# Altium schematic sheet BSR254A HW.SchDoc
size 431 x 279 mm; Date: Not shown in title block; ApprovedBy: Not shown in title block; CheckedBy: Not shown in title block; Author: Not shown in title block; CompanyName: Not shown in title block; DrawnBy: Tony Jacobs; Engineer: Not shown in title block; Organization: Not shown in title block; Address1: Not shown in title block; Address2: Not shown in title block; Address3: Not shown in title block; Address4: Not shown in title block; DocumentNumber: 2; Revision: Use project parameter SCH_Rev; SheetNumber: 2; SheetTotal: 2; PageSetup: Record=PageOptions¦CenterHorizontal=True¦CenterVertical=True¦PrintScale=1.00¦XCorrection=1.00¦YCorrection=1.00¦PrintKind=0¦BorderSize=5000000¦LeftOffset=0¦BottomOffset=0¦Orientation=2¦PaperLength=1000¦PaperWidth=1000¦Scale=100¦PaperSource=15¦PrintQuality=600¦MediaType=1¦DitherType=10¦PaperKind=Letter¦PrintScaleMode=1
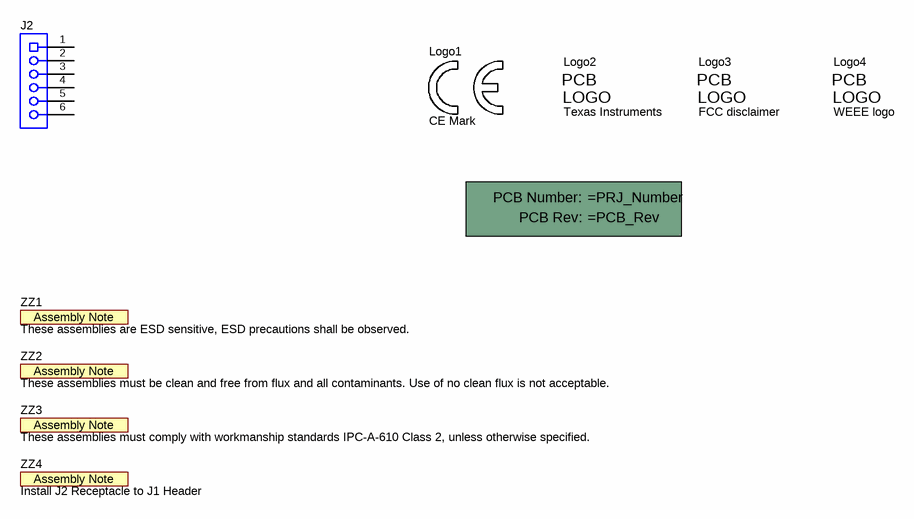
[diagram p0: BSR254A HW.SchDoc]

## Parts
!PCB1  Printed Circuit Board  (value not drawn)  (mechanical)
J2  SSW-106-01-G-S  [Samtec_SSW-106-01-x-S]  (value not drawn)  (mechanical)
Logo1  CE Mark  [CE_Mark_5mm]  (no BOM)
Logo2  Texas Instruments  [TI_Symbol_Overlay_Small]  (no BOM)
Logo3  FCC disclaimer  [FCC_disclaimer]  (no BOM)
Logo4  WEEE logo  [WEEE_Minimum]  (no BOM)
ZZ1  These assemblies are ESD sensitive, ESD precautions shall be observed.  [AssemblyNote]  (no BOM)
ZZ2  These assemblies must be clean and free from flux and all contaminants. Use of no clean flux is not acceptable.  [AssemblyNote]  (no BOM)
ZZ3  These assemblies must comply with workmanship standards IPC-A-610 Class 2, unless otherwise specified.  [AssemblyNote]  (no BOM)
ZZ4  Install J2 Receptacle to J1 Header  [AssemblyNote]  (no BOM)

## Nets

Not connected (* = marked no-connect by the designer): J2 1 2 3 4 5 6

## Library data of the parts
!PCB1 = CMP-0003618-2: Manufacturer: Any
J2 = CMP-0079953-1: Receptacle, 6x1, 2.54mm, Gold, TH; Manufacturer: Samtec; Current_A: 4.7A; Gender: Female; Cert_CSA: Y; Voltage_V: 465V; CompType: Socket Strip; Row_Count: 1; Pitch_mm: 2.54
Logo1 = CMP-0074844-1: SymbolCreator: a0412235
Logo2 = CMP-0074838-1: Texas Instrument Corporate Signature; SymbolCreator: a0412235; Lib Reference: TI_Logo
Logo3 = CMP-0074847-1: FCC_disclaimer
Logo4 = CMP-0074769-1
ZZ1 = CMP-0077236-1
ZZ2 = CMP-0077237-1
ZZ3 ZZ4 = CMP-0077238-1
